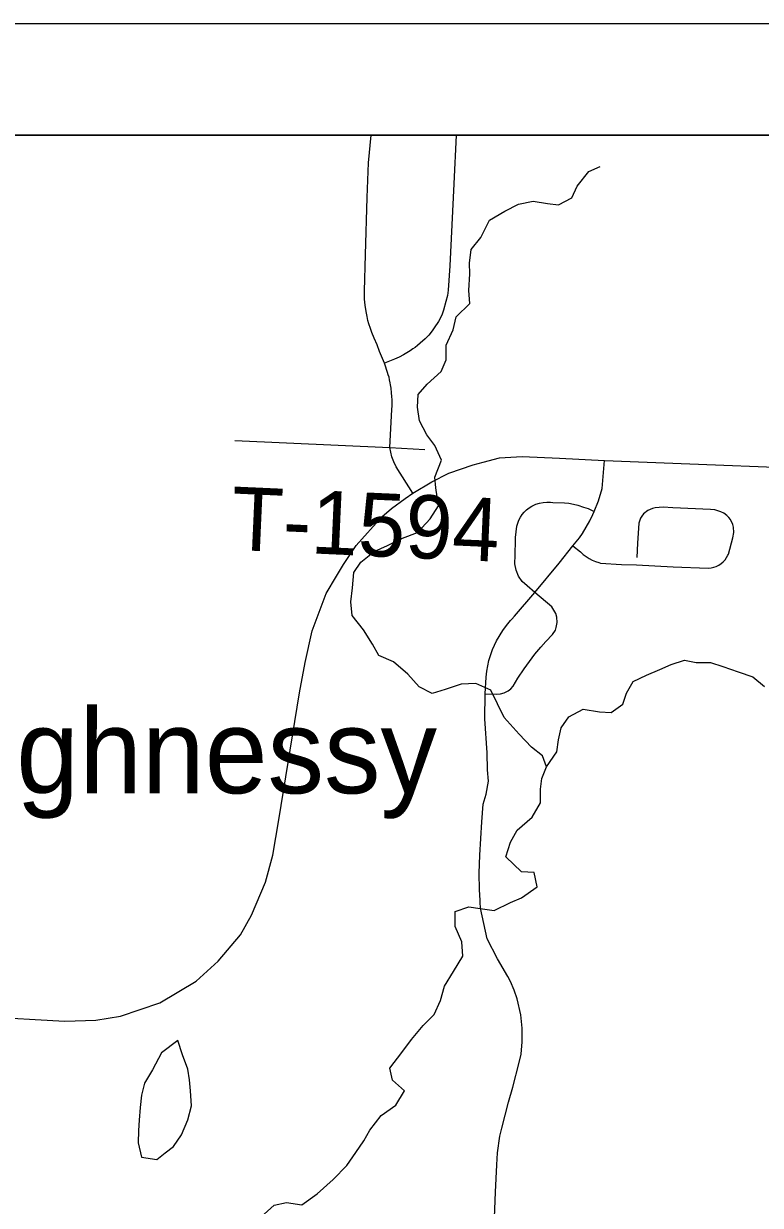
# Model space of a CAD drawing. Extents: x 0 to 34, y 0 to 22.
# Drawn here: x 14.062 to 14.723, y 9.224 to 10.284 of the extents above; entities that cross this region are included whole.
import ezdxf

# ---------------------------------------------------------------- set-up
doc = ezdxf.new("R2010")
doc.units = 0
for name, color, linetype in [('GM_X_Corporation', 7, 'Continuous'), ('GM_X_Hydro_Text', 7, 'Continuous'), ('GM_X_Minor_Lake', 7, 'Continuous'), ('GM_X_Minor_River', 7, 'Continuous'), ('GM_X_State_Route', 7, 'Continuous'), ('GM_X_Township_Road', 7, 'Continuous'), ('GM_X_Township_Road_Text', 7, 'Continuous'), ('SH_Data', 7, 'Continuous')]:
    doc.layers.add(name, color=color, linetype=linetype)

msp = doc.modelspace()

# ---------------------------------------------------------------- linework, layer by layer
at = {"layer": 'GM_X_Corporation'}
for points in [[(19.5646, 10.1841), (12.7646, 10.1841), (12.7646, 8.6719), (12.7953, 8.6676), (12.8119, 8.6756), (12.8296, 8.6783), (12.8448, 8.6761), (12.8988, 8.6726), (13.0467, 8.6615), (13.1161, 8.6564), (13.1948, 8.6507), (13.3525, 8.6386), (13.4613, 8.6292), (13.7169, 8.6042), (13.795, 8.6047), (14.2608, 8.5815), (14.4977, 8.5718), (14.6084, 8.5661), (14.9063, 8.5471), (15.334, 8.5309), (15.3473, 8.5302), (16.0546, 8.4904)], [(17.9872, 10.1841), (13.2832, 10.1841)]]:
    msp.add_lwpolyline(points, dxfattribs=at)
at = {"layer": 'GM_X_Minor_Lake'}
for points in [[(14.2002, 9.3715), (14.1858, 9.3605), (14.1775, 9.3453), (14.1703, 9.3332), (14.1677, 9.3225), (14.1666, 9.3115), (14.1658, 9.3002), (14.1651, 9.2907), (14.1647, 9.2797), (14.1677, 9.2668), (14.1814, 9.2649), (14.1891, 9.2709)], [(14.1891, 9.2709), (14.1965, 9.2766), (14.2037, 9.2869), (14.2093, 9.3005), (14.2127, 9.313), (14.2116, 9.3263), (14.2108, 9.3362), (14.2093, 9.346), (14.2044, 9.3586), (14.2002, 9.3715)]]:
    msp.add_lwpolyline(points, dxfattribs=at)
at = {"layer": 'GM_X_Minor_River'}
for points in [[(14.5309, 9.6172), (14.5275, 9.6271), (14.5176, 9.6347), (14.5066, 9.6465), (14.493, 9.6616), (14.4809, 9.6859), (14.4676, 9.692), (14.4544, 9.6913), (14.44, 9.6867), (14.4283, 9.6829), (14.4169, 9.689), (14.4067, 9.7004), (14.3938, 9.7114), (14.3806, 9.7171), (14.3749, 9.7273), (14.3669, 9.7402), (14.3567, 9.7531), (14.3556, 9.7653), (14.3571, 9.7778), (14.3582, 9.7915), (14.3646, 9.8009), (14.3764, 9.8104), (14.3885, 9.8157), (14.4017, 9.8225), (14.4153, 9.8275), (14.4267, 9.8396), (14.4342, 9.8514), (14.4316, 9.8677), (14.4308, 9.8772), (14.4369, 9.8923), (14.4308, 9.9056), (14.4236, 9.9151), (14.4172, 9.9276), (14.4153, 9.9398), (14.416, 9.9512), (14.424, 9.9606), (14.4365, 9.972), (14.441, 9.9823), (14.441, 9.9955), (14.4474, 10.0092), (14.4501, 10.021), (14.4622, 10.0331), (14.4614, 10.0445), (14.4622, 10.0597), (14.4618, 10.0691), (14.4633, 10.0813), (14.472, 10.0923), (14.4799, 10.1078), (14.4935, 10.1158), (14.506, 10.1222), (14.5189, 10.1249), (14.5318, 10.1226), (14.5416, 10.1215), (14.5537, 10.1279), (14.5586, 10.1382), (14.5688, 10.1514), (14.5791, 10.156)], [(14.5086, 9.5231), (14.4946, 9.5364), (14.4987, 9.5497), (14.5048, 9.5603), (14.518, 9.5721), (14.5256, 9.585), (14.5256, 9.5971), (14.5267, 9.6066), (14.5309, 9.6172), (14.5403, 9.6305), (14.5418, 9.6415), (14.5441, 9.6521), (14.5509, 9.662), (14.5638, 9.6688), (14.5785, 9.6665), (14.5891, 9.6658), (14.5994, 9.6734), (14.6028, 9.6832), (14.6088, 9.6939), (14.6205, 9.6995), (14.6326, 9.7045), (14.6429, 9.709), (14.6546, 9.7128), (14.6652, 9.7109), (14.6781, 9.7109), (14.689, 9.7071), (14.703, 9.7025), (14.7159, 9.698), (14.7265, 9.6893)], [(14.2749, 9.2132), (14.2866, 9.2238), (14.2979, 9.2261), (14.3116, 9.2242), (14.3252, 9.2341), (14.3396, 9.247), (14.352, 9.2595), (14.36, 9.2712), (14.3672, 9.2815), (14.3725, 9.291), (14.3827, 9.3043), (14.3959, 9.3137), (14.4035, 9.3263), (14.3929, 9.3361), (14.3906, 9.3467), (14.4012, 9.3608), (14.4099, 9.3725), (14.4205, 9.3851), (14.4303, 9.3949), (14.436, 9.4074), (14.4394, 9.4203), (14.4477, 9.4336), (14.456, 9.4473), (14.4549, 9.4602), (14.4492, 9.4738), (14.4492, 9.4875), (14.4613, 9.4917), (14.4715, 9.4901), (14.484, 9.4882), (14.4988, 9.4954), (14.5086, 9.4996), (14.5226, 9.5095), (14.52, 9.5224), (14.5086, 9.5231)]]:
    msp.add_lwpolyline(points, dxfattribs=at)
at = {"layer": 'GM_X_State_Route'}
for points in [[(14.4741, 9.8907), (14.4887, 9.8946), (14.509, 9.8957), (14.5425, 9.8941), (14.583, 9.892), (14.8278, 9.8824), (14.8534, 9.8809), (14.9413, 9.8772), (15.0831, 9.8702), (15.088, 9.87)], [(14.411, 9.8627), (14.428, 9.8728), (14.4435, 9.8808), (14.4653, 9.8883), (14.4741, 9.8907)], [(14.3427, 9.7884), (14.3488, 9.7988), (14.3603, 9.8158), (14.3834, 9.8416), (14.392, 9.849), (14.4041, 9.8581), (14.411, 9.8627)], [(13.5833, 9.5609), (13.6775, 9.4636), (13.6992, 9.4427), (13.7324, 9.4227), (13.7698, 9.4104), (13.8068, 9.4048), (13.8451, 9.4036), (14.0723, 9.3904), (14.0991, 9.3891), (14.1268, 9.39), (14.1489, 9.3934), (14.1842, 9.4053), (14.2169, 9.4248), (14.2365, 9.4427), (14.2565, 9.4665), (14.2663, 9.484), (14.2791, 9.5138), (14.2854, 9.538), (14.291, 9.5695), (14.3093, 9.6835), (14.3144, 9.7107), (14.3208, 9.7392), (14.3335, 9.7728), (14.3427, 9.7884)]]:
    msp.add_lwpolyline(points, dxfattribs=at)
at = {"layer": 'GM_X_Township_Road'}
for points in [[(14.3856, 9.9793), (14.3813, 9.9898), (14.379, 9.9958), (14.3765, 10.002), (14.3744, 10.007), (14.3732, 10.0104), (14.3717, 10.0147), (14.3708, 10.0178), (14.37, 10.0213), (14.3691, 10.0259), (14.3683, 10.0314), (14.3678, 10.0368), (14.3677, 10.0408), (14.3677, 10.0442), (14.3679, 10.0547), (14.3683, 10.0662), (14.3686, 10.0767), (14.3702, 10.1282), (14.3712, 10.1593), (14.3738, 10.1841)], [(14.4499, 10.1841), (14.4478, 10.1404), (14.4444, 10.0668), (14.4427, 10.0449), (14.4421, 10.04), (14.4407, 10.0348), (14.4387, 10.0271), (14.437, 10.0226), (14.434, 10.0168), (14.4303, 10.0112), (14.4284, 10.0084), (14.4254, 10.0047), (14.422, 10.0014), (14.4178, 9.9975), (14.4152, 9.9952), (14.4131, 9.9936), (14.4112, 9.9922), (14.4087, 9.9905), (14.4058, 9.9887), (14.4027, 9.9869), (14.3989, 9.9849), (14.3947, 9.9831), (14.3856, 9.9793)], [(14.411, 9.8627), (14.3962, 9.8864), (14.394, 9.8908), (14.3923, 9.8955), (14.3906, 9.9037), (14.3924, 9.9378), (14.3926, 9.9412), (14.3925, 9.9465), (14.3923, 9.9495), (14.3921, 9.9527), (14.3916, 9.9571), (14.3912, 9.9599), (14.3908, 9.9619), (14.3902, 9.9645), (14.3898, 9.9668), (14.389, 9.9691), (14.3884, 9.9712), (14.3876, 9.9737), (14.3869, 9.9759), (14.3856, 9.9793)], [(14.2514, 9.91), (14.3906, 9.9037), (14.4219, 9.9021)], [(14.5726, 9.8436), (14.5738, 9.8462), (14.5777, 9.8558), (14.5808, 9.867), (14.583, 9.892)], [(14.5205, 9.7737), (14.5135, 9.7795), (14.5092, 9.7835), (14.5059, 9.7883), (14.5037, 9.7936), (14.5026, 9.7993), (14.5025, 9.8013), (14.5028, 9.8051), (14.5033, 9.8229), (14.5044, 9.8332), (14.5052, 9.8359), (14.5062, 9.8386), (14.5076, 9.8412), (14.5092, 9.8435), (14.511, 9.8458), (14.513, 9.8478), (14.5153, 9.8496), (14.5177, 9.8511), (14.5203, 9.8524), (14.5214, 9.8528), (14.5247, 9.8537), (14.5279, 9.8543), (14.5313, 9.8546), (14.5346, 9.8546), (14.5365, 9.8545), (14.547, 9.8541), (14.5511, 9.8537), (14.5551, 9.853), (14.5591, 9.852), (14.5642, 9.8503), (14.5683, 9.8489), (14.5738, 9.8462)], [(14.4998, 9.7498), (14.5023, 9.7525), (14.5205, 9.7737), (14.5422, 9.8), (14.5547, 9.8155), (14.5605, 9.8227), (14.5633, 9.8267), (14.5698, 9.8378), (14.5726, 9.8436)], [(14.5547, 9.8155), (14.5616, 9.8101), (14.5639, 9.8078), (14.5664, 9.8058), (14.5691, 9.8041), (14.5719, 9.8026), (14.5749, 9.8014), (14.5779, 9.8005), (14.5795, 9.8001), (14.5981, 9.7988), (14.6116, 9.7986), (14.6446, 9.7966), (14.676, 9.7956), (14.6785, 9.7958), (14.6809, 9.7963), (14.6832, 9.7971), (14.6855, 9.7982), (14.6877, 9.7997), (14.6894, 9.8011), (14.6911, 9.8029), (14.6925, 9.8049), (14.6937, 9.8071), (14.6941, 9.808), (14.6982, 9.8227), (14.699, 9.8274), (14.6987, 9.8323), (14.698, 9.8346), (14.6959, 9.839), (14.6945, 9.841), (14.6928, 9.8427), (14.6901, 9.8448), (14.6874, 9.8461), (14.6818, 9.8477), (14.6779, 9.8481), (14.6444, 9.8496), (14.6355, 9.8501), (14.6283, 9.8497), (14.626, 9.8491), (14.6218, 9.8471), (14.6181, 9.8441), (14.6166, 9.8422), (14.6154, 9.8402), (14.6137, 9.8358), (14.6125, 9.818), (14.6121, 9.8049)], [(14.476, 9.6828), (14.4865, 9.6824), (14.4897, 9.6826), (14.4929, 9.6835), (14.4967, 9.6854), (14.4991, 9.6873), (14.501, 9.6896), (14.5054, 9.6967), (14.5108, 9.7051), (14.5156, 9.7118), (14.5206, 9.7184), (14.5259, 9.7247), (14.5303, 9.7296), (14.5363, 9.7359), (14.5389, 9.7399), (14.5397, 9.7421), (14.5406, 9.7468), (14.5402, 9.7515), (14.5392, 9.7547), (14.5357, 9.7607), (14.5205, 9.7737)], [(14.4731, 9.5677), (14.4741, 9.5836), (14.4769, 9.5926), (14.479, 9.6042), (14.478, 9.6145), (14.4779, 9.6297), (14.4757, 9.6602), (14.476, 9.6828), (14.4768, 9.6977), (14.4774, 9.703), (14.4792, 9.7126), (14.4826, 9.7226), (14.4862, 9.7302), (14.4919, 9.7396), (14.4951, 9.7441), (14.4986, 9.7484), (14.4998, 9.7498)], [(14.4715, 9.4976), (14.4709, 9.5067), (14.4706, 9.5217), (14.4712, 9.538), (14.4731, 9.5677)], [(14.4827, 9.1746), (14.4851, 9.2354), (14.4864, 9.2599), (14.4871, 9.2707), (14.4892, 9.2858), (14.4908, 9.293), (14.4969, 9.3163), (14.5008, 9.3297), (14.5066, 9.3519), (14.5081, 9.3593), (14.5092, 9.3704), (14.5091, 9.3828), (14.508, 9.3947), (14.5046, 9.4091), (14.502, 9.4169), (14.4987, 9.4245), (14.4964, 9.4291), (14.4869, 9.4449), (14.4777, 9.4629), (14.4719, 9.4905), (14.4716, 9.4956), (14.4715, 9.4976)]]:
    msp.add_lwpolyline(points, dxfattribs=at)
at = {"layer": 'SH_Data'}
for p, q in [((12.6646, 10.2841), (19.6646, 10.2841)), ((12.7646, 10.1841), (19.5646, 10.1841))]:
    msp.add_line(p, q, dxfattribs=at)

# ---------------------------------------------------------------- texts
at = {"layer": 'GM_X_Hydro_Text'}
msp.add_text("O'Shaughnessy", height=0.075758, rotation=0.0053, dxfattribs=at).set_placement((13.7207, 9.5934))
at = {"layer": 'GM_X_Township_Road_Text'}
msp.add_text('T-1594', height=0.05682, rotation=357.4298, dxfattribs=at).set_placement((14.2472, 9.812))

doc.saveas('drawing.dxf')
